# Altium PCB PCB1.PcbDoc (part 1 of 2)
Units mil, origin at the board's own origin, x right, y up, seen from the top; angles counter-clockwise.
Board outline 3937.01 x 3937.01 mil, 4 copper layers (Top Layer, Layer 1, Layer 2, Bottom Layer), stack 68.734 mil thick; 96 components, 71 nets, 353 pads, 281 vias.
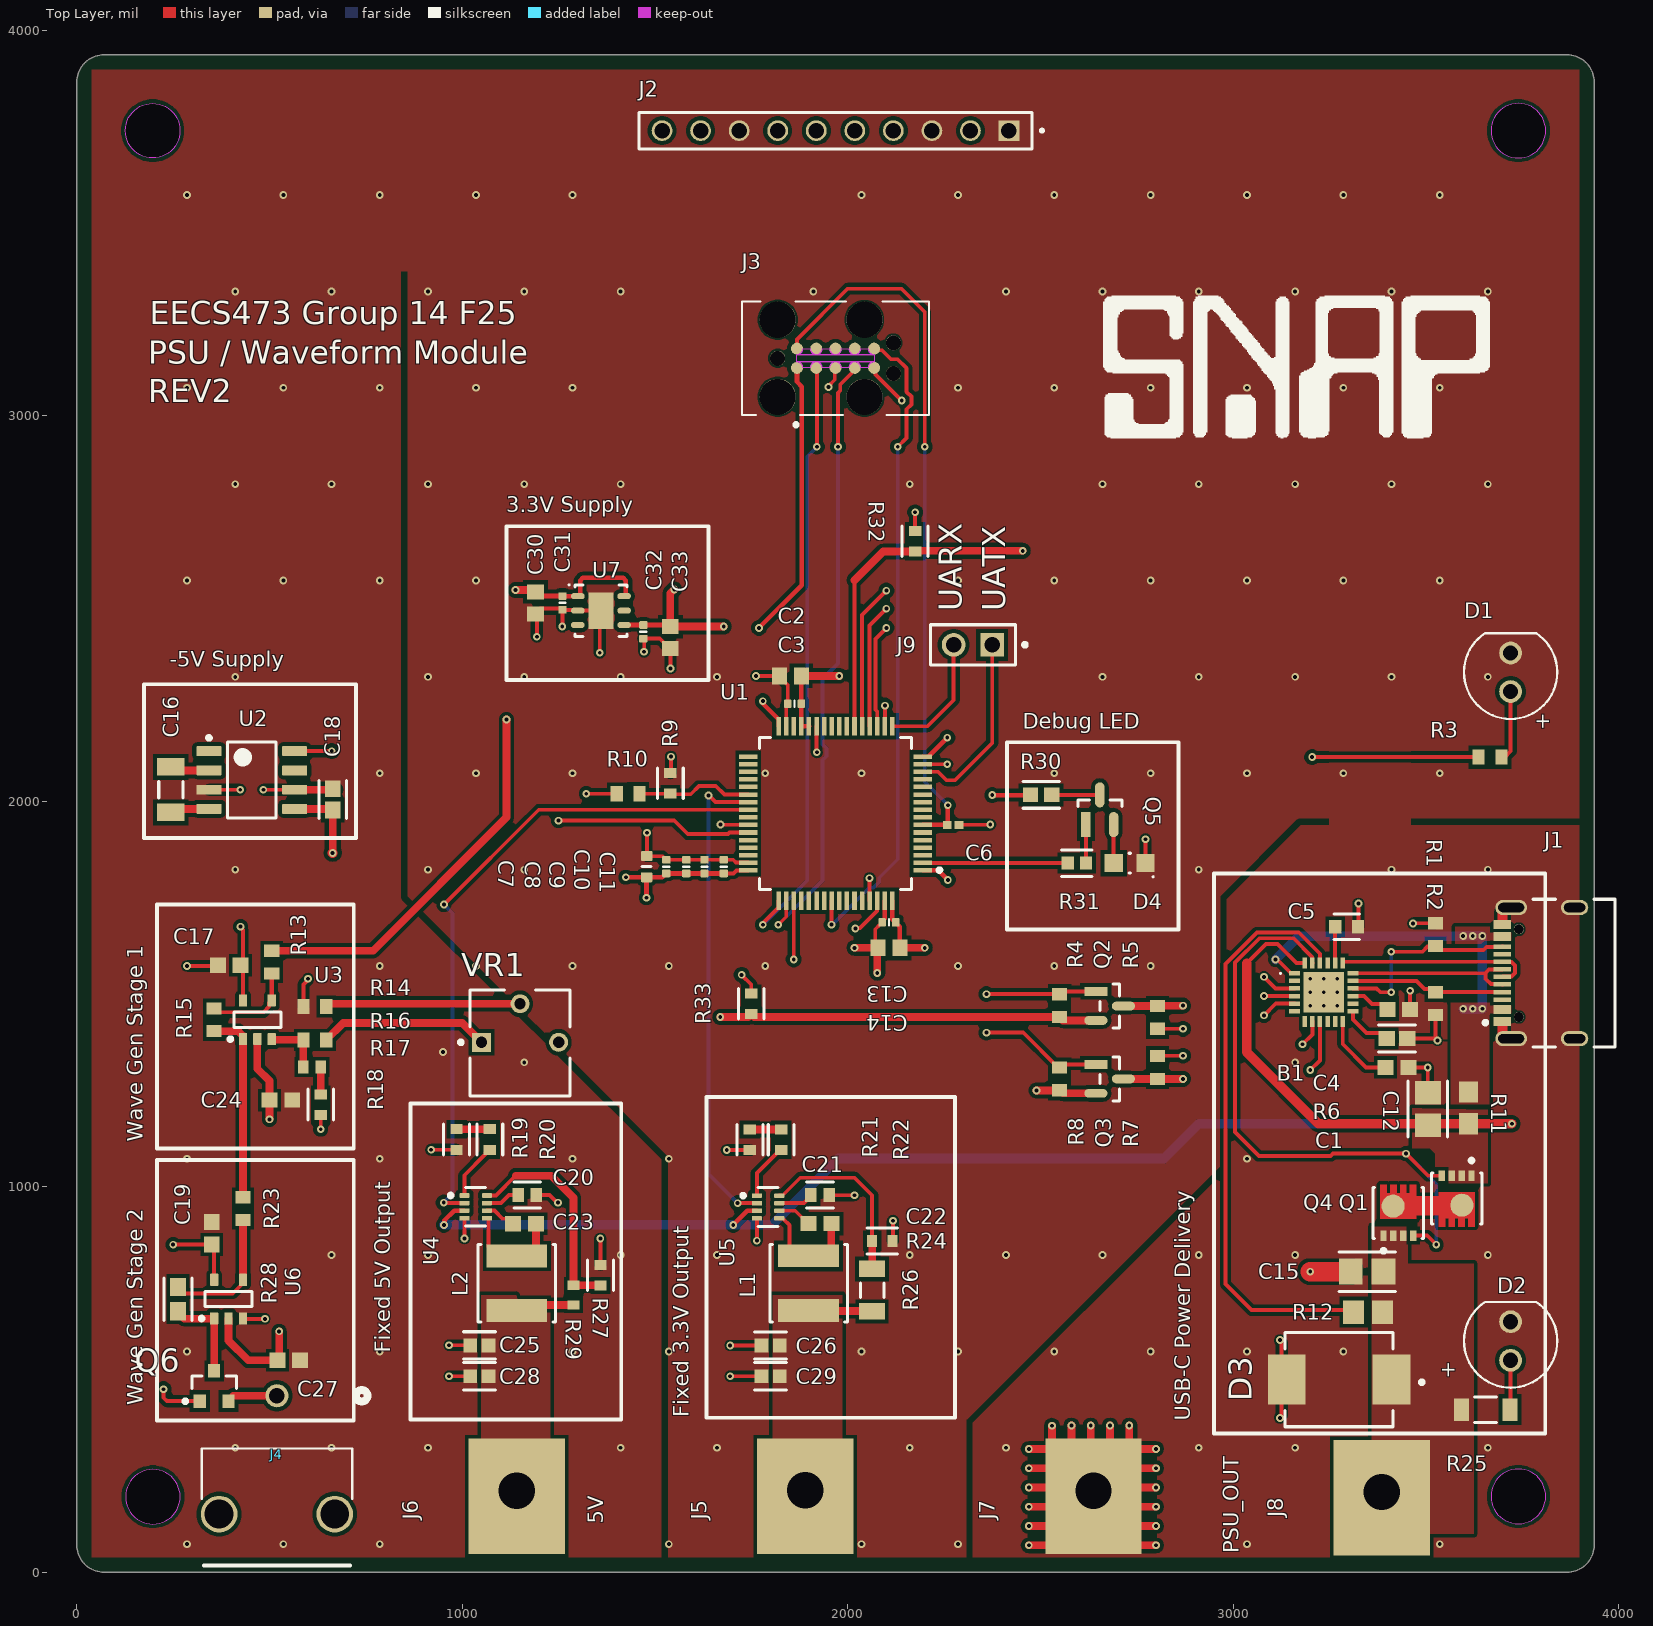
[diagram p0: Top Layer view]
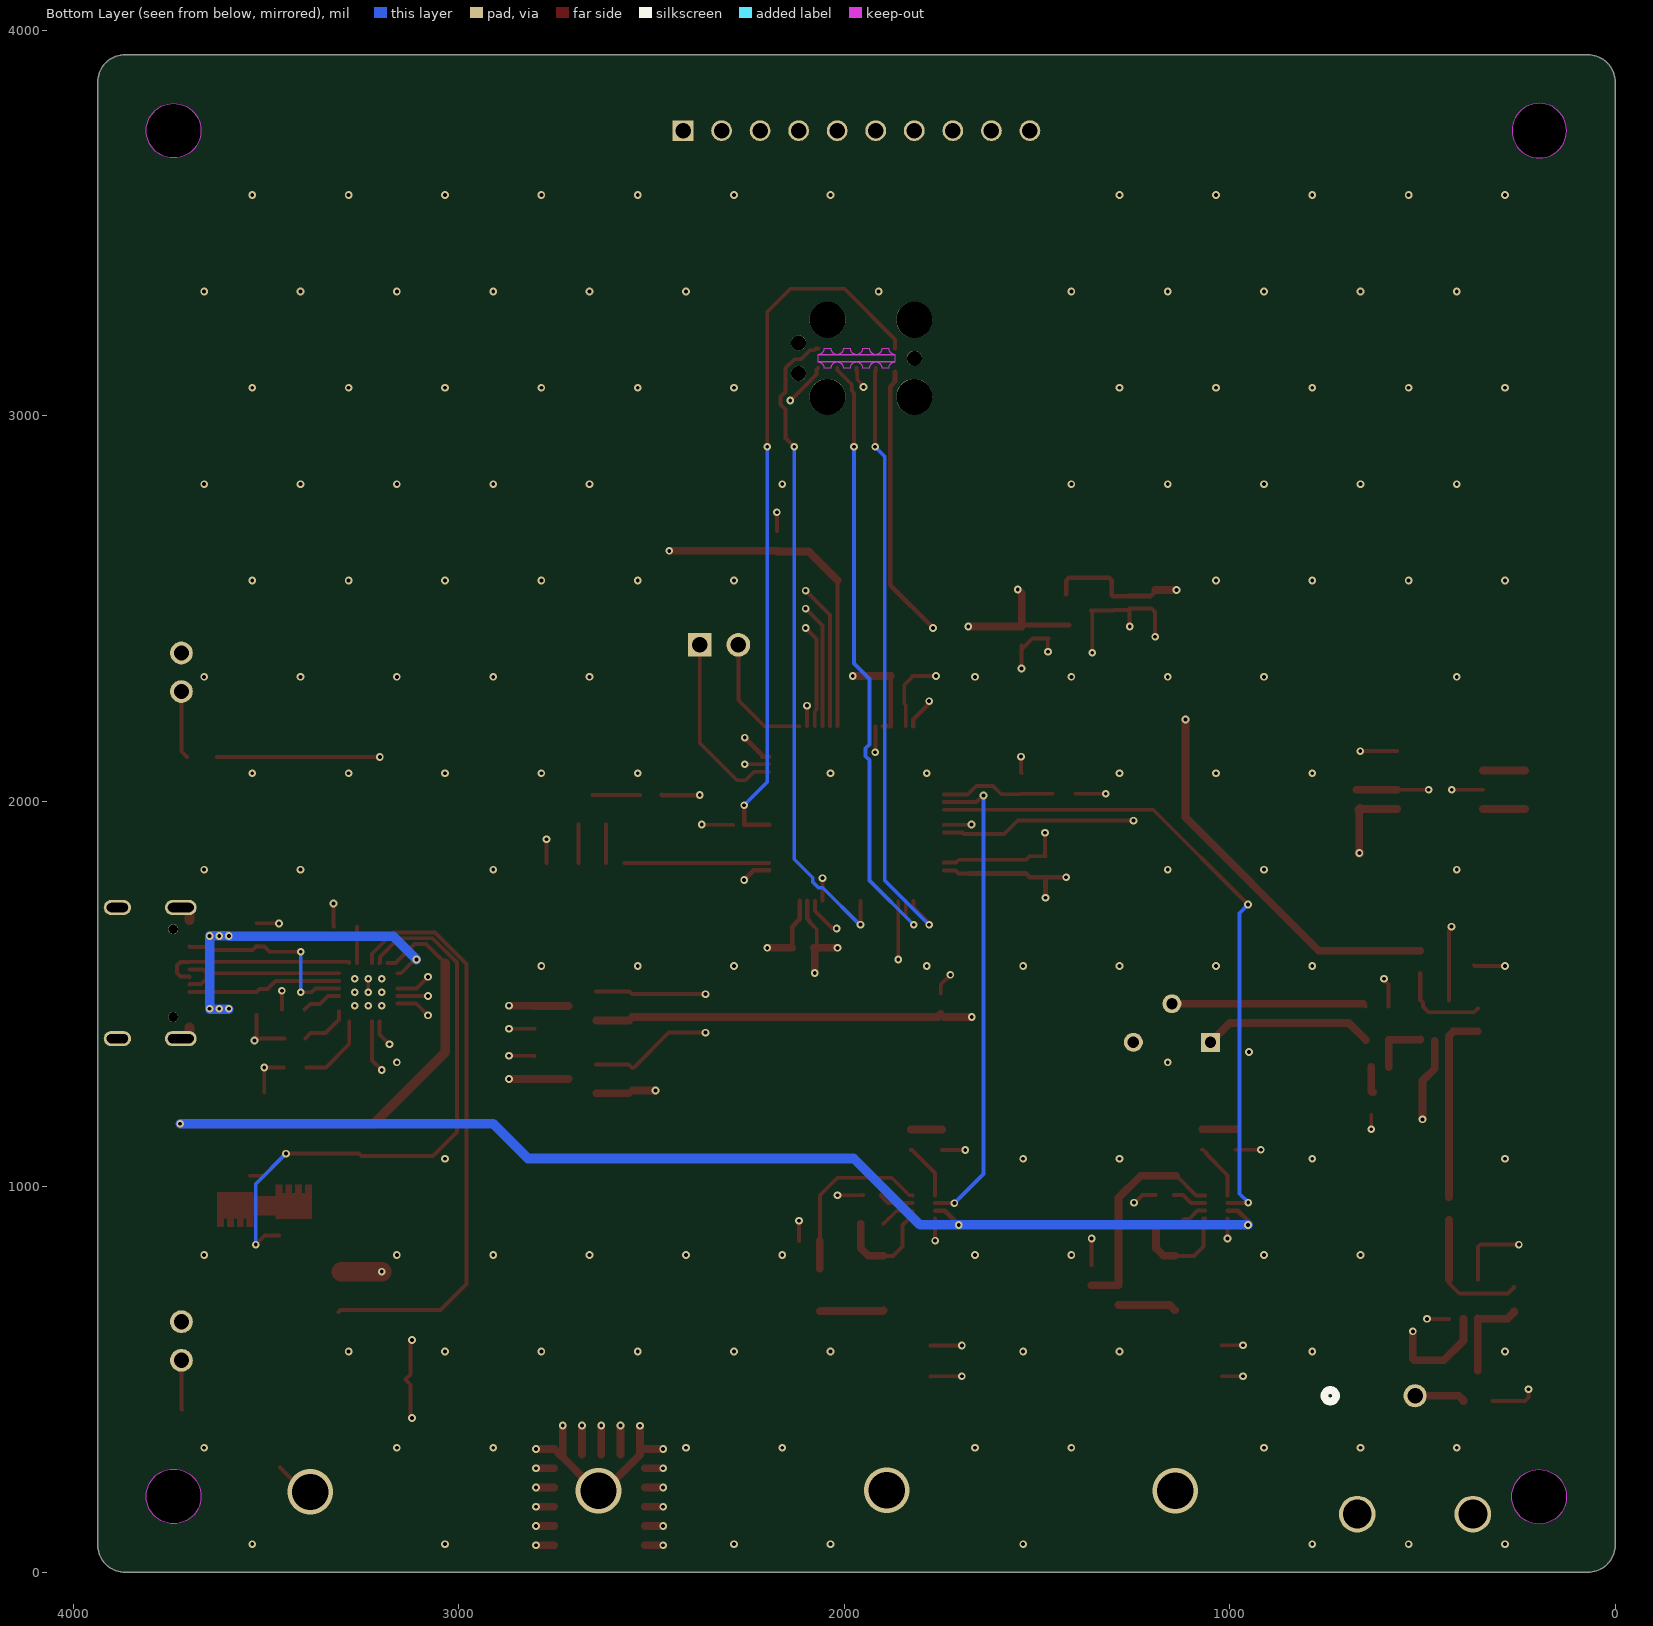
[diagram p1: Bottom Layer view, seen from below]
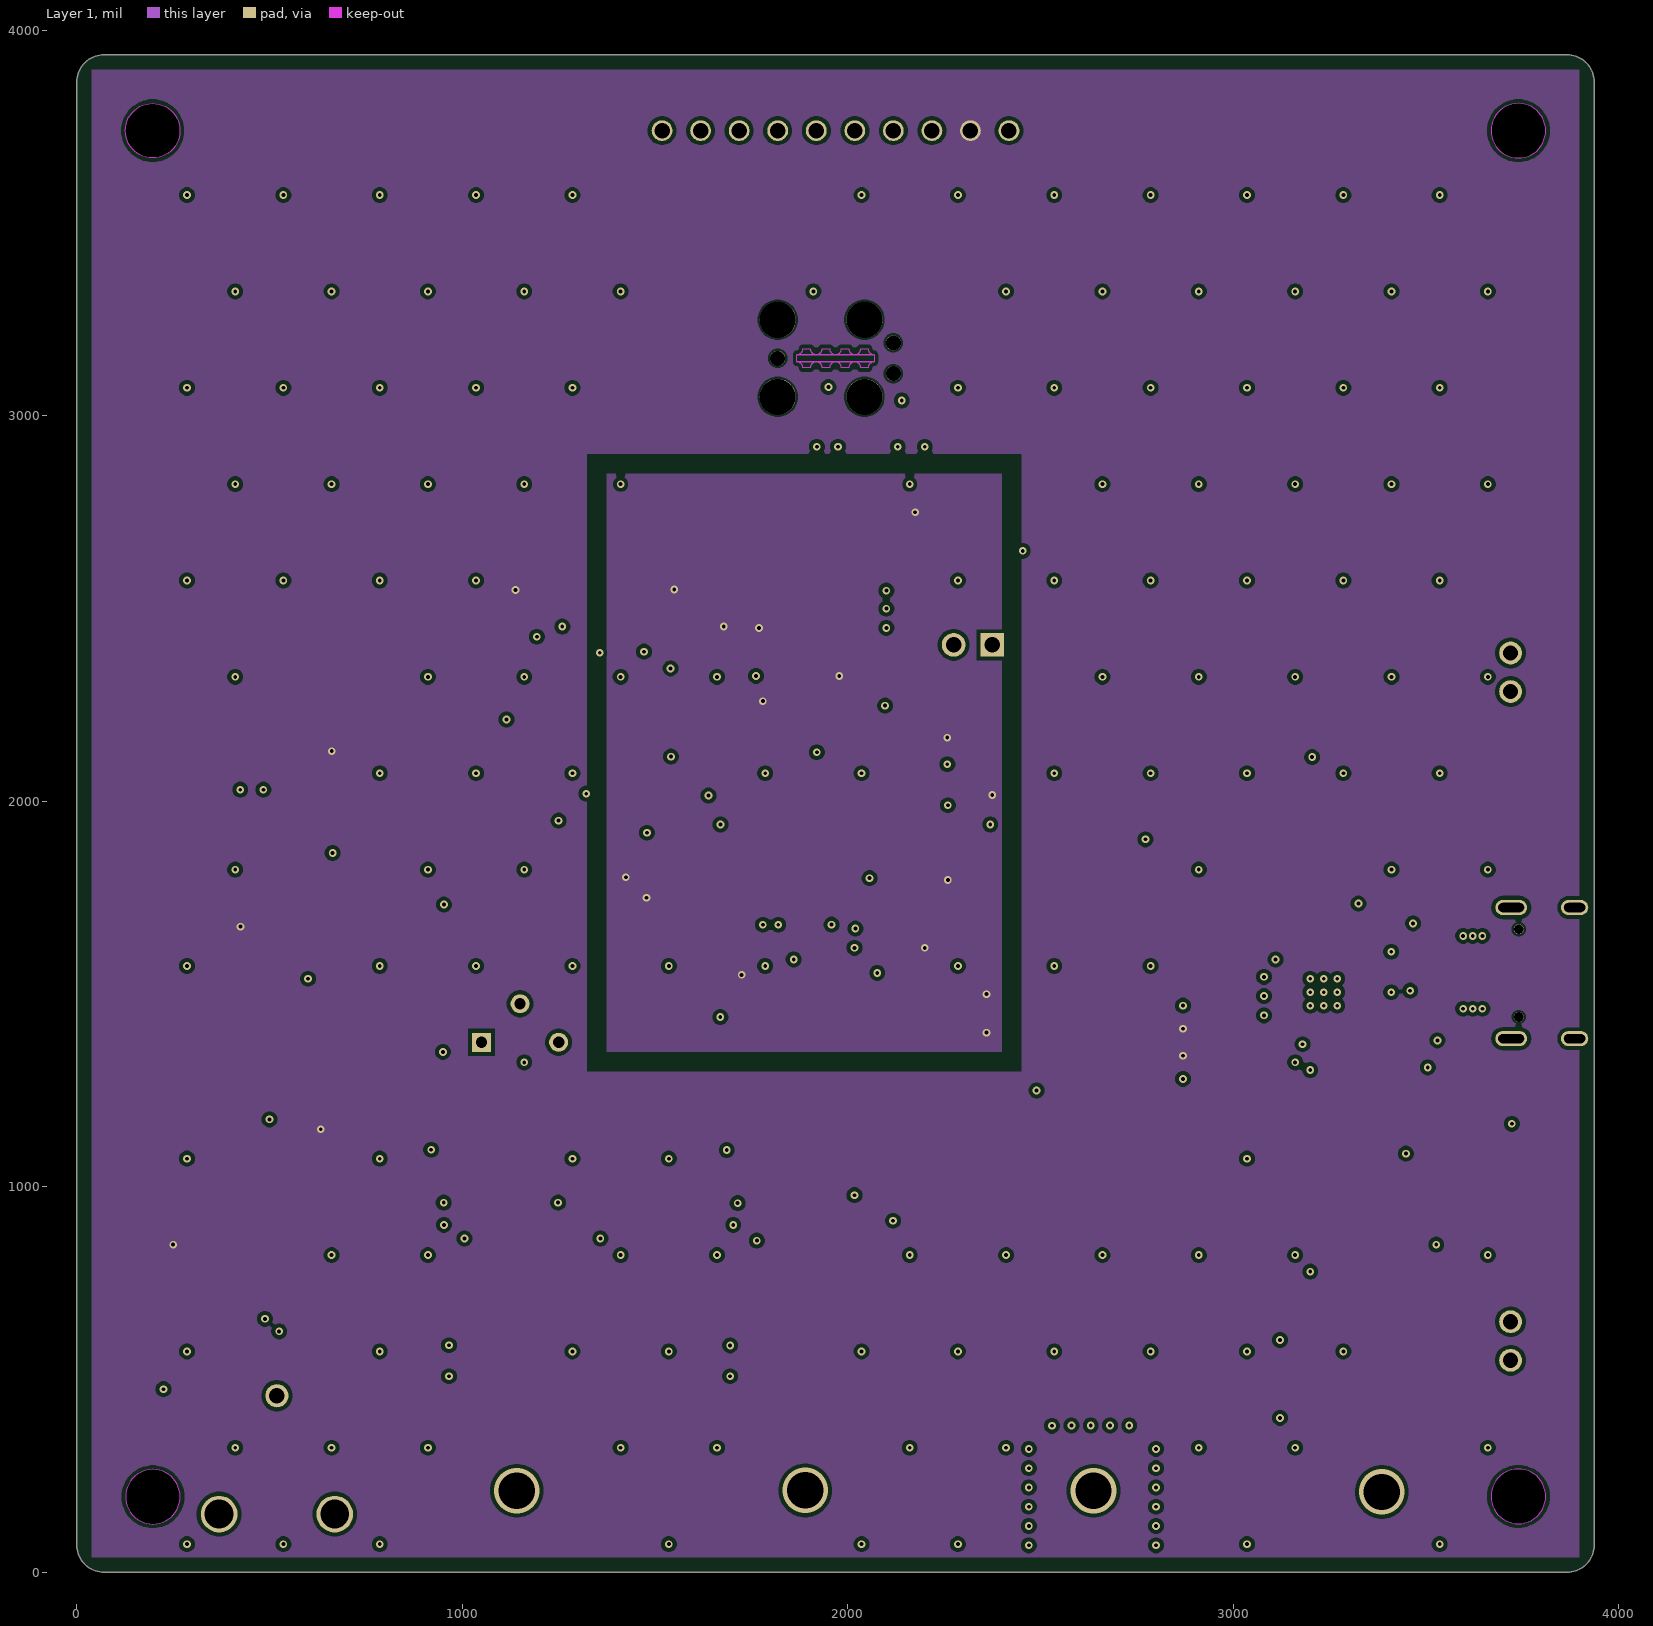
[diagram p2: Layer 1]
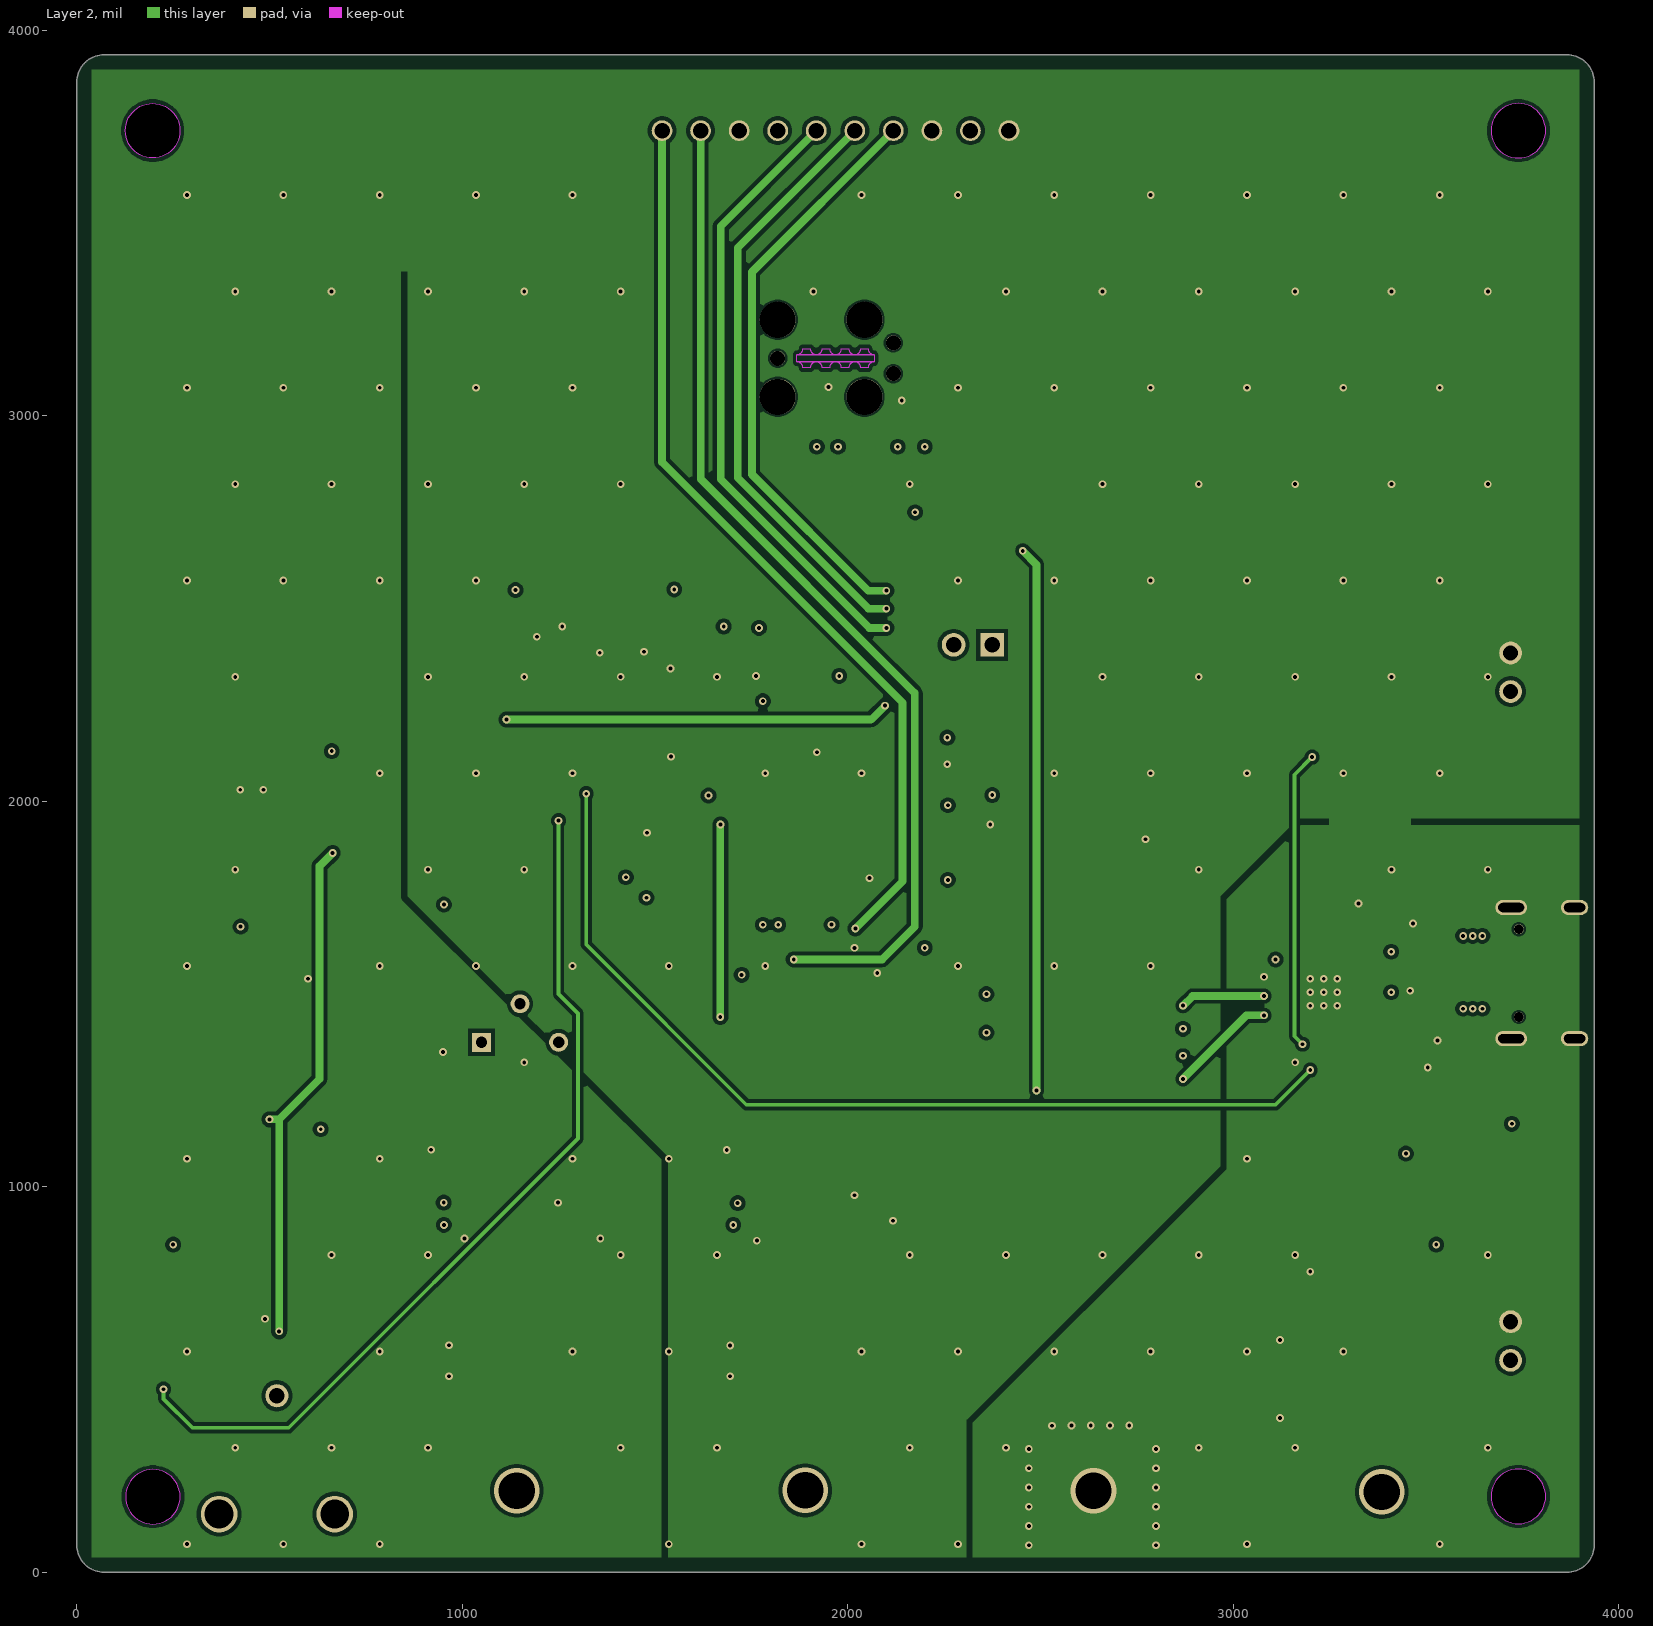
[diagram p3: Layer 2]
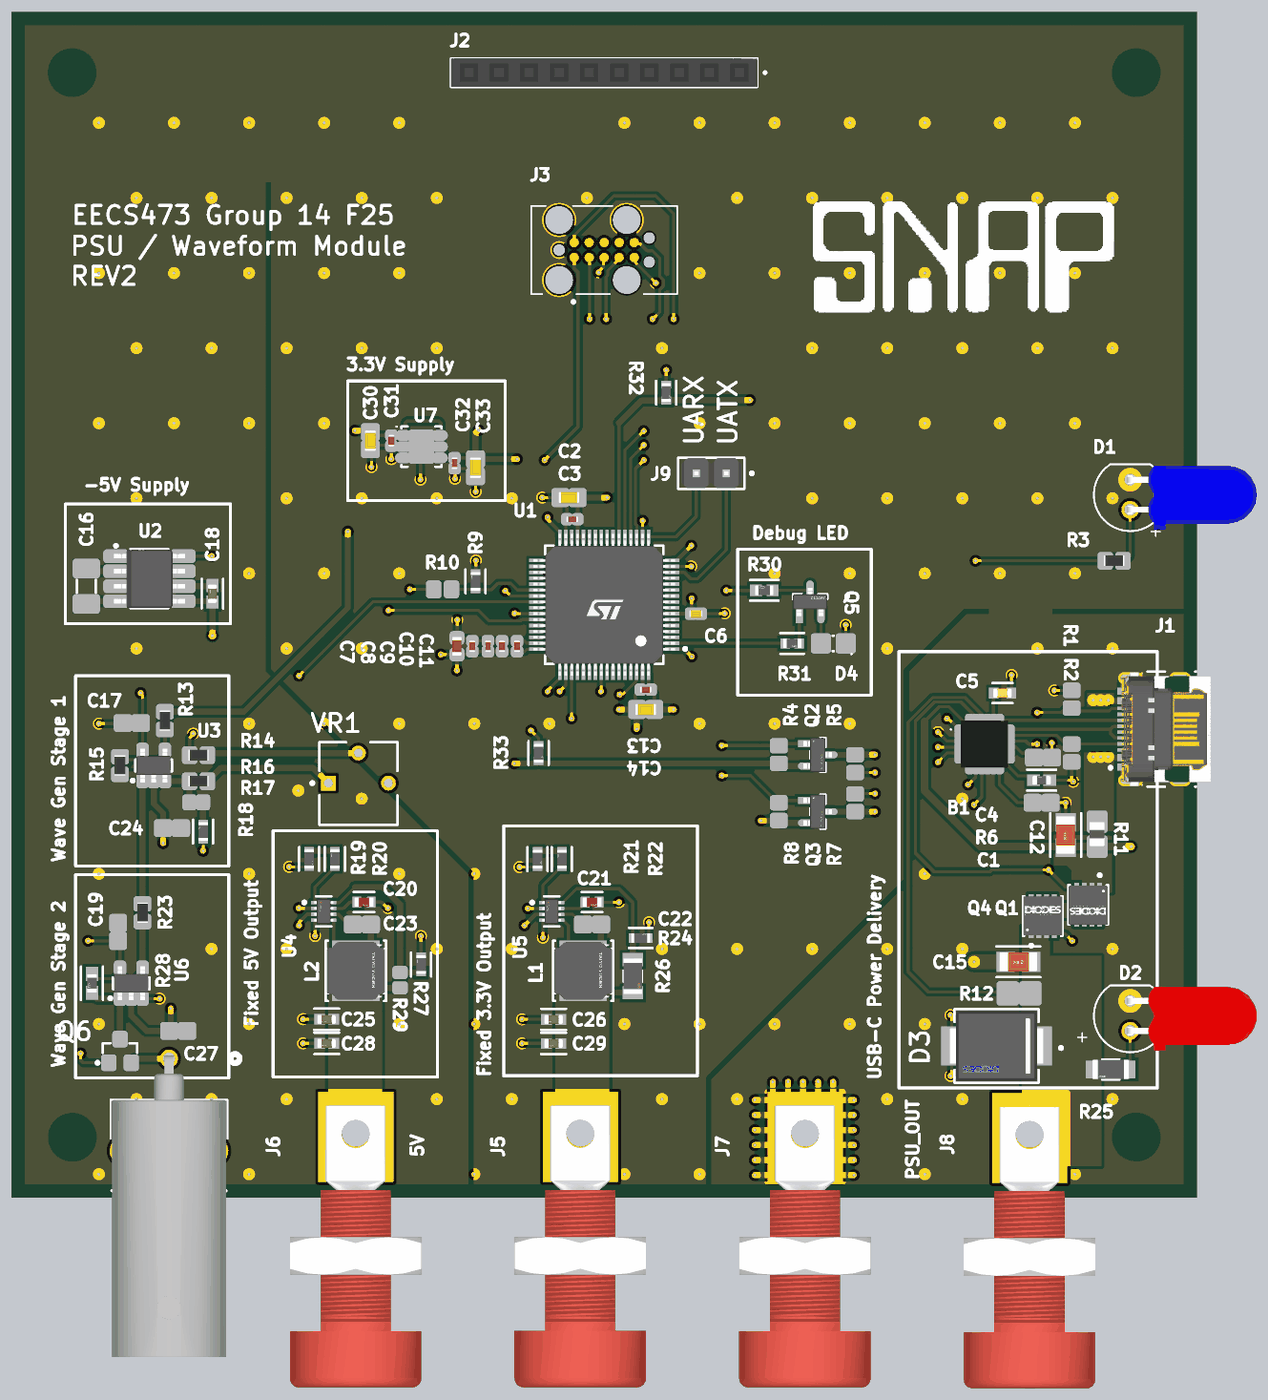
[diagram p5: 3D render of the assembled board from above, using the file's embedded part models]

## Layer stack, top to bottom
Top Solder: solder mask 0.5, Solder Resist, Dk 3.3
Top Layer: signal copper 1.378
Dielectric 1: prepreg 2.8, PP-006, Dk 4.1
Layer 1: signal copper 0.689
Dielectric1: core 59, FR-4, Dk 4.3
Layer 2: signal copper 0.689
Dielectric 2: prepreg 2.8, PP-006, Dk 4.1
Bottom Layer: signal copper 1.378
Bottom Solder: solder mask 0.5, Solder Resist, Dk 3.3

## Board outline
0,70.87 ccw(c70.87,70.87) 70.87,0 3866.14,0 ccw(c3866.14,70.87) 3937.01,70.87 3937.01,3866.14 ccw(c3866.14,3866.14) 3866.14,3937.01 70.87,3937.01 ccw(c70.87,3866.14) 0,3866.14
cut-out: 3669.29,3740.16 ccw(c3740.16,3740.16) 3740.16,3669.29 ccw(c3740.16,3740.16) 3811.02,3740.16 ccw(c3740.16,3740.16) 3740.16,3811.02 ccw(c3740.16,3740.16)
cut-out: 3669.29,196.85 ccw(c3740.16,196.85) 3740.16,125.98 ccw(c3740.16,196.85) 3811.02,196.85 ccw(c3740.16,196.85) 3740.16,267.72 ccw(c3740.16,196.85)
cut-out: 126.69,196.07 ccw(c197.56,196.07) 197.56,125.2 ccw(c197.56,196.07) 268.42,196.07 ccw(c197.56,196.07) 197.56,266.94 ccw(c197.56,196.07)
cut-out: 196.85,3669.29 cw(c196.85,3740.16) 125.98,3740.16 cw(c196.85,3740.16) 196.85,3811.02 cw(c196.85,3740.16) 267.72,3740.16 cw(c196.85,3740.16)

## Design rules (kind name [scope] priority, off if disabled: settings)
Clearance "Stitching GND" [IsStitchingVia and InNet('GND') vs (IsVia and (Not IsStitchingVia)) Or IsPad] p1: gap=5 ignorepadtopadclearanceinfootprint=FALSE
Clearance [All] p2: gap=10 ignorepadtopadclearanceinfootprint=FALSE except(3: Arc-Hole Track-Hole; 5: Arc-Arc Arc-Track Arc-SMDPad Track-Track Track-SMDPad SMDPad-SMDPad SMDPad-Hole THPad-Hole Via-Hole Fill-Hole Poly-Hole Region-Hole Text-Hole)
DiffPairsRouting [All] p1: maxlimit=10 minlimit=10 mostfreqgap=10 toplayer_minwidth=10 toplayer_maxwidth=10 toplayer_prefwidth=10 midlayer1_minwidth=10 midlayer1_maxwidth=10 midlayer1_prefwidth=10 midlayer2_minwidth=10 midlayer2_maxwidth=10 midlayer2_prefwidth=10 bottomlayer_minwidth=10 bottomlayer_maxwidth=10 bottomlayer_prefwidth=10 maxuncoupledlength=500
HoleSize [All] p1: absolutevalues=TRUE maxlimit=300 minlimit=6 maxpercent=80.000 minpercent=20.000
MinimumAnnularRing [All] p1: minimumring=5
PasteMaskExpansion [All] p1: expansion=10
PlaneClearance [All] p1: clearance=15
PlaneConnect [All] p1: pad.planeconnectstyle=Relief pad.reliefexpansion=20 pad.reliefentries=4 pad.reliefconductorwidth=10 pad.reliefairgap=10 via.planeconnectstyle=Direct via.reliefexpansion=20 via.reliefentries=4 via.reliefconductorwidth=10 via.reliefairgap=10
PolygonConnect PolygonConnect_1 [InNet('VBUS_SNS')] p1: connectstyle=Direct reliefconductorwidth=10 reliefentries=4 polygonreliefangle="90 Angle" airgapwidth=10
PolygonConnect PolygonConnect_5 [InNet('VBUS')] p2: connectstyle=Direct reliefconductorwidth=10 reliefentries=4 polygonreliefangle="90 Angle" airgapwidth=10
PolygonConnect PolygonConnect_4 [InNet('PSU_OUT')] p3: connectstyle=Direct reliefconductorwidth=10 reliefentries=4 polygonreliefangle="90 Angle" airgapwidth=10
PolygonConnect PolygonConnect_3 [InNet('NetC10_2')] p4: connectstyle=Direct reliefconductorwidth=10 reliefentries=4 polygonreliefangle="90 Angle" airgapwidth=10
PolygonConnect PolygonConnect_2 [InNet('NetC6_2')] p5: connectstyle=Direct reliefconductorwidth=10 reliefentries=4 polygonreliefangle="90 Angle" airgapwidth=10
PolygonConnect [All] p6: connectstyle=Direct reliefconductorwidth=10 reliefentries=4 polygonreliefangle="90 Angle" airgapwidth=10
RoutingVias [All] p1: holewidth=10 width=20 viastyle="Through Hole" minholewidth=10 minwidth=20 maxholewidth=10 maxwidth=20
SMDNeckDown [All] p1: percent=120.000
SilkToSolderMaskClearance SilkscreenOverComponentPads [IsPad] p1: minsilkscreentomaskgap=4 clearancetoexposedcopper=TRUE
SolderMaskExpansion [All] p1: expansion=10 istentingtop=FALSE
SupplyNets "Schematic Supply Nets_2" [InNet('-5')] p1: voltage=0.000
SupplyNets "Schematic Supply Nets_5" [InNet('GND')] p2: voltage=0.000
SupplyNets "Schematic Supply Nets_4" [InNet('3V3')] p3: voltage=0.000
SupplyNets "Schematic Supply Nets" [InNet('+5')] p4: voltage=0.000
Width [All] p1: maxlimit=50 minlimit=10 preferedwidth=20 minimp=50.000000 maximp=50.000000 favimp=50.000000
24 further rules are at their usual default settings.

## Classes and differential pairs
component class WG1: C16 C17 C18 C19 C24 C27 Q6 R13 R14 R15 R16 R17 R18 R23 R28 U2 U3 U6 VR1
component class TopLevel: J2 J4 J5 J6 J7 J8 J9 R32 R33
component class MCU1: C2 C3 C6 C7 C8 C9 C10 C11 C13 C14 C30 C31 C32 C33 D4 J3 Q5 R30 R31 U1 U7
component class PS1: B1 C1 C4 C5 C12 C15 C20 C21 C22 C23 C25 C26 C28 C29 D1 D2 D3 J1 L1 L2 Q1 Q2 Q3 Q4 R1 R2 R3 R4 R5 R6 R7 R8 R9 R10 R11 R12 R19 R20 R21 R22 R24 R25 R26 R27 R29 U4 U5

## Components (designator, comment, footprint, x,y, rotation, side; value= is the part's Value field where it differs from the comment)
B1 "AP33772S" AP33772SDKZ13FA01 3235.16,1504.84 r0 top
C1 ".1uF" CAPC1608X90X35NL15T15 3425.16,1309.84 r0 top
C2 "Capacitor 1uF +/- 10% 16V 0603" CAPC1608X90X35ML15T15 1851.38,2325.49 r0 top value=1µF
C3 "Capacitor 100nF +/-20% 10V 0402" CAPC0402(1005)60_L 1862.2,2253.38 r0 top value=100nF
C4 ".1uF" CAPC1608X90X35NL15T15 3429.68,1459.84 r180 top
C5 "1uF" FP-CC0603-DA-MFG 3294.69,1674.84 r0 top value="1 uF"
C6 "Capacitor 0.1 uF +/- 5% 16 V 0402" CAPC1005X56X25LL10T15 2273.86,1938.98 r180 top value=100nF
C7 "Capacitor 4.7µF +/-20% 10V 0603" CAPC0603(1608)100_L 1478.5,1830.71 r270 top value=4.7µF
C8 "Capacitor 100nF +/-20% 10V 0402" CAPC0402(1005)60_L 1529.49,1830.71 r270 top value=100nF
C9 "Capacitor 100nF +/-20% 10V 0402" CAPC0402(1005)60_L 1581.34,1830.71 r270 top value=100nF
C10 "Capacitor 100nF +/-20% 10V 0402" CAPC0402(1005)60_L 1628.5,1830.71 r270 top value=100nF
C11 "Capacitor 100nF +/-20% 10V 0402" CAPC0402(1005)60_L 1678.5,1830.71 r270 top value=100nF
C12 "10uF" FP-C3216-160-0_2-IPC_C 3505.16,1202.21 r90 top
C13 "Capacitor 100nF +/-20% 10V 0402" CAPC0402(1005)60_L 2107.01,1686.06 r0 top value=100nF
C14 "Capacitor 1uF +/- 10% 16V 0603" CAPC1608X90X35ML15T15 2107.01,1620 r0 top value=1µF
C15 "10uF" FP-C3216-160-0_2-IPC_C 3347.83,780.03 r180 top
C16 "CAP 47uF 10V 1206(3216)" CAPC1206(3216)190_N 244.14,2030.35 r90 top value=47uF
C17 ".1uF" CAPC1608X90X35NL15T15 395.47,1575 r0 top
C18 "10uF" FP-GRM188-0_2-IPC_B 664.14,2005.35 r90 top
C19 ".1uF" CAPC1608X90X35NL15T15 350,879.53 r270 top
C20 "33nF" FP-C0603C333J4REC7411-MFG 1168.73,979 r0 top
C21 "33nF" FP-C0603C333J4REC7411-MFG 1928.12,978.76 r0 top
C22 ".1uF" CAPC1608X90X35NL15T15 1928.12,904.46 r0 top
C23 ".1uF" CAPC1608X90X35NL15T15 1161.73,904 r0 top
C24 ".1uF" CAPC1608X90X35NL15T15 529.53,1225 r180 top
C25 "22uF" FP-GRM188-0_2-IPC_C 1044.41,588.59 r180 top
C26 "22uF" FP-GRM188-0_2-IPC_C 1800.07,588.36 r180 top
C27 ".1uF" CAPC1608X90X35NL15T15 550,550 r180 top
C28 "22uF" FP-GRM188-0_2-IPC_C 1044.41,508.59 r180 top
C29 "22uF" FP-GRM188-0_2-IPC_C 1800.07,508.36 r180 top
C30 "Capacitor 1uF +/- 10% 16V 0603" CAPC1608X90X35ML15T15 1190,2515 r90 top value=1µF
C31 "Capacitor 100nF +/-20% 10V 0402" CAPC0402(1005)60_L 1260,2515 r90 top value=100nF
C32 "Capacitor 100nF +/-20% 10V 0402" CAPC0402(1005)60_L 1470,2440 r90 top value=100nF
C33 "Capacitor 1uF +/- 10% 16V 0603" CAPC1608X90X35ML15T15 1540,2425 r90 top value=1µF
D1 "5mm Blue LED" WL-TMRC_D5.9H8.7 3720,2334.99 r90 top
D2 "5mm Red LED" WL-TMRC_D5.9H8.7 3720.01,599.99 r90 top
D3 "B550C-13-F" FP-SMC-MFG 3275,500 r180 top
D4 "LTST-C170KGKT" LTST-LTST-C170KGKT-2_V 2731.46,1839.89 r180 top
J1 "USB4105-GF-A" FP-USB4105-GF-A-MFG 3840.16,1554.53 r90 top
J2 "SSQ-110-04-G-S" SAMTEC_SSQ-110-04-G-S 1968.5,3740.16 r180 top
J3 "TC2050-IDC" TAG-CONNECT_TC2050-IDC 1968.5,3149.61 r0 top
J4 "731713150" CONN_731713150_MOL 519.29,457.9 r0 top
J5 "108-0902-001" FP-108-0902-001-MFG 1889.76,262.27 r0 top
J6 "108-0902-001" FP-108-0902-001-MFG 1141.73,261.85 r0 top
J7 "108-0902-001" FP-108-0902-001-MFG 2637.8,261.85 r0 top
J8 "108-0902-001" FP-108-0902-001-MFG 3385.83,258.36 r0 top
J9 "M20-9990246" FP-M20-9990246-MFG 2325,2406.3 r180 top
L1 "3.3uH" FP-NR5040-H_4_1-MFG 1898.58,750.09 r270 top
L2 "3.3uH" FP-NR5040-H_4_1-MFG 1141.73,750 r270 top
Q1 "DMT6010LFG-7" FP-PowerDI3333-8-MFG 3580.16,969.84 r180 top
Q2 "BSS138" FP-318-08-IPC_B 2679.68,1469.06 r0 top
Q3 "BSS138" FP-318-08-IPC_B 2679.68,1280 r0 top
Q4 "DMT6010LFG-7" FP-PowerDI3333-8-MFG 3428.59,932.37 r0 top
Q5 "MMBT3904-7-F" FP-SOT23-IPC_A 2654.09,1978.35 r90 top
Q6 "BC818-40LT1G" ONSC-SOT-23-3-318-08_V 356.3,483.27 r90 top
R1 "5.1k" RESC1608X55X25ML10T15 3525.16,1654.37 r270 top
R2 "5.1k" RESC1608X55X25ML10T15 3525.16,1475.32 r90 top
R3 "Resistor 1k +/-1% 0603 100 mW" RESC1608X55X25ML10T15 3666.58,2115 r0 top value=1k
R4 "5.1k" RESC1608X55X25ML10T15 2550,1470 r90 top
R5 "5.1k" RESC1608X55X25ML10T15 2803.85,1439.53 r270 top
R6 "10k NTC" FP-NC_18-0_15-IPC_B 3425.16,1384.84 r180 top
R7 "5.1k" RESC1608X55X25ML10T15 2803.85,1309.53 r90 top
R8 "5.1k" RESC1608X55X25ML10T15 2550,1280 r90 top
R9 "10k" FP-RC0603-0_55-IPC_C 1540,2046.64 r90 top
R10 "5.1k" RESC1608X55X25ML10T15 1430.47,2020 r180 top
R11 "ERJ6LWFR005V" RES_ERJ6LWFR005V 3610.16,1204.84 r270 top value=5m
R12 "100" RESC2013X60X40ML20T25 3350,675 r0 top
R13 "Resistor 1k +/-1% 0603 100 mW" RESC1608X55X25ML10T15 505.91,1583.07 r90 top value=1k
R14 "Resistor 1k +/-1% 0603 100 mW" RESC1608X55X25ML10T15 617.68,1467.99 r180 top value=1k
R15 "Resistor 1k +/-1% 0603 100 mW" RESC1608X55X25ML10T15 356.3,1433.54 r90 top value=1k
R16 "Resistor 1k +/-1% 0603 100 mW" RESC1608X55X25ML10T15 617.68,1381.09 r0 top value=1k
R17 "100" RESC1609X50X30LL10T20 610.15,1311.06 r180 top
R18 "10k" FP-RC0603-0_55-IPC_C 632.79,1213.54 r90 top
R19 "10k" FP-RC0603-0_55-IPC_C 985.35,1122.77 r270 top
R20 "10k" FP-RC0603-0_55-IPC_C 1071.7,1122.77 r90 top
R21 "10k" FP-RC0603-0_55-IPC_C 1746.34,1122.04 r270 top
R22 "10k" FP-RC0603-0_55-IPC_C 1827.4,1122.04 r90 top
R23 "Resistor 1k +/-1% 0603 100 mW" RESC1608X55X25ML10T15 431.1,943.38 r90 top value=1k
R24 "10k" FP-RC0603-0_55-IPC_C 2090.18,859.51 r0 top
R25 "5k" FP-RT1206-0_65-MFG 3655.24,421.73 r180 top value=5kΩ
R26 "31.2k" FP-TFCR1206-IPC_B 2063.54,732.18 r270 top
R27 "10k" FP-RC0603-0_55-IPC_C 1358.73,771 r90 top
R28 "3k" FP-RMCF0603-IPC_A 262.76,708.66 r270 top
R29 "52.3k" RESC1608X55X25LL10T15 1288.73,719 r270 top
R30 "510R" FP-RMCF0603-IPC_B 2501.71,2016.8 r180 top
R31 "2k" FP-RMCF0603-IPC_C 2594.41,1839.89 r0 top
R32 "10k" FP-RC0603-0_55-IPC_C 2175,2675 r270 top
R33 "10k" FP-RC0603-0_55-IPC_C 1750,1475 r270 top
U1 "STM32G474RET6" FP-LQFP64-5W-MFG 1968.5,1968.5 r180 top
U2 "LM2663MX/NOPB" D0008A_M 454.14,2055.35 r0 top
U3 "OPA192IDBVR" DBV0005A_L 468.5,1433.54 r90 top
U4 "XTPS62933DRLR" FP-DRL0008A-MFG 1034.73,948 r0 top
U5 "XTPS62933DRLR" FP-DRL0008A-MFG 1793.54,947.76 r0 top
U6 "OPA192IDBVR" DBV0005A_L 393.7,708.66 r90 top
U7 "LD39050PU33R" DFN6D_M 1360,2495 r0 top
VR1 "3362P-1-103LF" BOUR-3362P 1150,1373.62 r0 top

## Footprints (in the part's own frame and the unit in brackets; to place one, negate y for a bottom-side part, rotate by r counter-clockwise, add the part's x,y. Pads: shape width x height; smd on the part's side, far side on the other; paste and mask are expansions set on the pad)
AP33772SDKZ13FA01 [mm]
  rect 0.75x0.3 smd: 1(-1.925,1.25) 2(-1.925,0.75) 3(-1.925,0.25) 4(-1.925,-0.25) 5(-1.925,-0.75) 6(-1.925,-1.25) 13(1.925,-1.25) 14(1.925,-0.75) 15(1.925,-0.25) 16(1.925,0.25) 17(1.925,0.75) 18(1.925,1.25)
  rect 0.3x0.75 smd: 7(-1.25,-1.925) 8(-0.75,-1.925) 9(-0.25,-1.925) 10(0.25,-1.925) 11(0.75,-1.925) 12(1.25,-1.925) 19(1.25,1.925) 20(0.75,1.925) 21(0.25,1.925) 22(-0.25,1.925) 23(-0.75,1.925) 24(-1.25,1.925)
  rect 2.7x2.7 smd: 25(0,0)
  silkscreen extent -2.9,1.2 -2.8,1.3, body extent -2,-2 2,2, height 0.75
BOUR-3362P [mm] "THD, 3-Leads, Body 6.6x6.99mm, Pitch 2.54mm"
  rect 1.25x1.25 hole 0.75: 1(-2.54,0.035)
  round 1.25 hole 0.75: 2(0,2.575) 3(2.54,0.035)
  silkscreen extent -4.02,-3.49 3.3,3.5, body extent -3.3,-3.49 3.3,3.49, height 4.95
CAPC0402(1005)60_L [mm] "Chip Capacitor, Body 1.0x0.5mm, Height 0.6mm, IPC High Density"
  rrect25% 0.5x0.55 smd: 1(-0.45,0) 2(0.45,0)
  silkscreen extent 0,-0.2 0,0.2, body extent -0.5,-0.25 0.5,0.25, height 0.6
CAPC0603(1608)100_L [mm] "Chip Capacitor, Body 1.6x0.8mm, Height 1.0mm, IPC High Density"
  rrect25% 0.66x0.76 smd: 1(-0.7,0) 2(0.7,0)
  silkscreen extent 0,-0.3 0,0.3, body extent -0.8,-0.4 0.8,0.4, height 0.95
CAPC1005X56X25LL10T15 [mm] "Chip Capacitor, 2-Leads, Body 1.10x0.60mm, IPC High Density"
  rect 0.58x0.54 smd: 1(-0.39,0) 2(0.39,0)
  body extent -0.55,-0.3 0.55,0.3, height 0.56
CAPC1206(3216)190_N [mm] "Chip Capacitor, Body 3.2x1.6mm, Height 1.9mm, IPC Medium Density"
  rect 1.15x1.8 smd: 1(-1.5,0) 2(1.5,0)
  silkscreen extent -0.55,-0.8 0.55,0.8, body extent -1.7,-0.9 1.7,0.9, height 1.9
CAPC1608X90X35ML15T15 [mm] "Chip Capacitor, 2-Leads, Body 1.75x0.95mm, IPC Low Density"
  rect 1x1.1 smd: 1(-0.725,0) 2(0.725,0)
  body extent -0.87,-0.48 0.87,0.48, height 0.9
CAPC1608X90X35NL15T15 [mm] "Chip Capacitor, 2-Leads, Body 1.60x0.81mm, IPC Medium Density"
  rect 1.05x1 smd: 1(-0.75,0) 2(0.75,0)
  body extent -0.88,-0.48 0.87,0.48, height 0.9
CONN_731713150_MOL [mil]
  round 60 hole 40: 1(0,0)
  round 95 hole 75: 2(-150,-307) 3(150,-307)
  silkscreen extent -195,-440 235,15, body extent -190,-996 190,10, height 368
D0008A_M [mm] "SOIC, 8-Leads, Body 5x4mm, Pitch 1.27mm, IPC Low Density"
  rrect15% 1.65x0.65 smd: 1(-2.825,1.905) 2(-2.825,0.635) 3(-2.825,-0.635) 4(-2.825,-1.905) 5(2.825,-1.905) 6(2.825,-0.635) 7(2.825,0.635) 8(2.825,1.905)
  silkscreen extent -2.95,-2.5 1.6,2.9, body extent -3,-2.45 3,2.45, height 1.63
DBV0005A_L [mm] "SOT23, 5-Leads, Body 3.05x1.75mm, Pitch 0.95mm, IPC High Density"
  rrect18% 0.8x0.55 smd: 1(-1.275,0.95) 2(-1.275,0) 3(-1.275,-0.95) 4(1.275,-0.95) 5(1.275,0.95)
  silkscreen extent -1.4,-1.55 0.5,1.9, body extent -1.42,-1.46 1.42,1.46, height 1.08
DFN6D_M [mm] "SON, 6-Leads, Body 3x3mm, Pitch 0.95mm, Thermal Pad 2.4x1.65mm, IPC Low Density"
  oval 0.9x0.4 smd: 1(-1.525,0.95) 2(-1.525,0) 3(-1.525,-0.95) 4(1.525,-0.95) 5(1.525,0) 6(1.525,0.95)
  rect 1.65x2.4 smd: 7(0,0)
  silkscreen extent -2.15,-1.7 1.7,1.75, body extent -1.55,-1.55 1.55,1.55, height 0.95
FP-108-0902-001-MFG [mil]
  rect 250x300 / inner rect 0x0 / far side rect 0x0 all layers, no hole: 1(0,-65)
  body extent -220,-899 218,39, height 264
FP-318-08-IPC_B [mm]
  rect 1.524x0.578 smd paste+0 mask+0: 1(-0.91,0.95)
  rrect100% 1.524x0.578 smd paste+0 mask+0: 2(-0.91,-0.95) 3(0.91,0)
  silkscreen extent -0.65,-1.45 0.65,1.45, body extent -1.92,-1.7 1.92,1.7, height 0.25
FP-C0603C333J4REC7411-MFG [mm]
  rect 0.75x0.9 smd paste+0 mask+0: 1(-0.6,0) 2(0.6,0)
  silkscreen extent -0.87,-0.85 0.88,0.85, body extent -1.2,-0.6 1.2,0.6, height 0.25
FP-C3216-160-0_2-IPC_C [mil]
  rect 61.18x67.17 smd paste+0 mask+0: 1(-42.37,0) 2(42.37,0)
  silkscreen extent -73,-51 73,51, body extent -77,-39 77,39, height 10
FP-CC0603-DA-MFG [mm]
  rect 0.8x0.9 smd paste+0 mask+0: 1(-0.75,0) 2(0.75,0)
  silkscreen extent -0.85,-0.85 0.85,0.85, body extent -1.35,-0.75 1.35,0.75, height 0.25
FP-DRL0008A-MFG [mm]
  rrect33% 0.67x0.3 smd paste+0 mask+0: 1(-0.74,0.75) 2(-0.74,0.25) 3(-0.74,-0.25) 4(-0.74,-0.75) 5(0.74,-0.75) 6(0.74,-0.25) 7(0.74,0.25) 8(0.74,0.75)
  silkscreen extent -1.77,-1.27 0.65,1.28, body extent -1.17,-1.35 1.17,1.35, height 0.25
FP-GRM188-0_2-IPC_B [mil]
  rect 43.51x39.61 smd paste+0 mask+0: 1(-27.58,0) 2(27.58,0)
  silkscreen extent -49,-36 49,36, body extent -59,-30 59,30, height 10
FP-GRM188-0_2-IPC_C [mil]
  rect 35.63x35.68 smd paste+0 mask+0: 1(-23.64,0) 2(23.64,0)
  silkscreen extent -41,-35 41,35, body extent -45,-24 45,24, height 10
FP-LQFP64-5W-MFG [mm]
  rect 1.2x0.3 smd paste+0 mask+0: 1(-5.75,3.75) 2(-5.75,3.25) 3(-5.75,2.75) 4(-5.75,2.25) 5(-5.75,1.75) 6(-5.75,1.25) 7(-5.75,0.75) 8(-5.75,0.25) 9(-5.75,-0.25) 10(-5.75,-0.75) 11(-5.75,-1.25) 12(-5.75,-1.75) 13(-5.75,-2.25) 14(-5.75,-2.75) 15(-5.75,-3.25) 16(-5.75,-3.75) 33(5.75,-3.75) 34(5.75,-3.25) 35(5.75,-2.75) 36(5.75,-2.25) 37(5.75,-1.75) 38(5.75,-1.25) 39(5.75,-0.75) 40(5.75,-0.25) 41(5.75,0.25) 42(5.75,0.75) 43(5.75,1.25) 44(5.75,1.75) 45(5.75,2.25) 46(5.75,2.75) 47(5.75,3.25) 48(5.75,3.75)
  rect 0.3x1.2 smd paste+0 mask+0: 17(-3.75,-5.75) 18(-3.25,-5.75) 19(-2.75,-5.75) 20(-2.25,-5.75) 21(-1.75,-5.75) 22(-1.25,-5.75) 23(-0.75,-5.75) 24(-0.25,-5.75) 25(0.25,-5.75) 26(0.75,-5.75) 27(1.25,-5.75) 28(1.75,-5.75) 29(2.25,-5.75) 30(2.75,-5.75) 31(3.25,-5.75) 32(3.75,-5.75) 49(3.75,5.75) 50(3.25,5.75) 51(2.75,5.75) 52(2.25,5.75) 53(1.75,5.75) 54(1.25,5.75) 55(0.75,5.75) 56(0.25,5.75) 57(-0.25,5.75) 58(-0.75,5.75) 59(-1.25,5.75) 60(-1.75,5.75) 61(-2.25,5.75) 62(-2.75,5.75) 63(-3.25,5.75) 64(-3.75,5.75)
  silkscreen extent -6.98,-5 5,5, body extent -6.45,-6.45 6.45,6.45, height 0.25
FP-M20-9990246-MFG [mm]
  rect 1.57x1.57 hole 1.02 paste-2539.97 mask+0: 1(-1.27,0)
  round 1.57 hole 1.02 paste-2539.97 mask+0: 2(1.27,0)
  silkscreen extent -3.55,-1.32 2.79,1.32, body extent -2.89,-1.42 2.89,1.42, height 0.25
FP-NC_18-0_15-IPC_B [mil]
  rect 43.55x37.73 smd paste+0 mask+0: 1(-26.62,0) 2(26.62,0)
  silkscreen extent -48,-35 48,35, body extent -58,-29 58,29, height 10
FP-NR5040-H_4_1-MFG [mm]
  rect 1.5x4 smd paste+0 mask+0: 1(-1.8,0) 2(1.8,0)
  silkscreen extent -2.55,-2.55 2.55,2.55, body extent -2.65,-2.65 2.65,2.65, height 0.25
FP-PowerDI3333-8-MFG [mm]
  rect 0.42x0.7 smd paste+0 mask+0: 1(-0.975,-1.5) 2(-0.325,-1.5) 3(0.325,-1.5) 4(0.975,-1.5)
  round 1.519 smd paste+0 mask+0: 5-6-7-8(-0.341,0.444)
  Top Layer region: -1.185,1.85 -0.765,1.85 -0.765,1.31 -0.535,1.31 -0.535,1.85 -0.115,1.85 -0.115,1.31 0.115,1.31 0.115,1.85 0.535,1.85 0.535,1.31 0.765,1.31 0.765,1.85 1.185,1.85 1.185,-0.4 -1.185,-0.4 -1.185,1.85
  silkscreen extent -1.68,-2.62 1.67,1.67, body extent -1.78,-1.95 1.78,1.95, height 0.25
FP-RC0603-0_55-IPC_C [mil]
  rect 25.93x31.97 smd paste+0 mask+0: 1(-26.64,0) 2(26.64,0)
  silkscreen extent -40,-33 40,33, body extent -44,-22 44,22, height 10
FP-RMCF0603-IPC_A [mil]
  rect 47.48x41.66 smd paste+0 mask+0: 1(-31.54,0) 2(31.54,0)
  silkscreen extent -55,-37 55,37, body extent -75,-41 75,41, height 10
FP-RMCF0603-IPC_B [mil]
  rect 39.61x37.73 smd paste+0 mask+0: 1(-27.6,0) 2(27.6,0)
  silkscreen extent -47,-35 47,35, body extent -57,-29 57,29, height 10
FP-RMCF0603-IPC_C [mil]
  rect 31.73x33.79 smd paste+0 mask+0: 1(-23.66,0) 2(23.66,0)
  silkscreen extent -40,-34 40,34, body extent -43,-23 43,23, height 10
FP-RT1206-0_65-MFG [mm]
  rect 1x1.5 smd paste+0 mask+0: 1(-1.6,0) 2(1.6,0)
  silkscreen extent -0.73,-0.85 0.72,0.85, body extent -2.2,-0.95 2.2,0.95, height 0.25
FP-SMC-MFG [mm]
  rect 2.5x3.3 smd paste+0 mask+0: 1(-3.45,0) 2(3.45,0)
  silkscreen extent -5.58,-3.11 3.55,3.11, body extent -4.8,-3.21 4.8,3.21, height 0.25
FP-SOT23-IPC_A [mm]
  rect 1.659x0.627 smd paste+0 mask+0: 1(-0.977,0.915)
  rrect100% 1.659x0.627 smd paste+0 mask+0: 2(-0.977,-0.915) 3(0.977,0)
  silkscreen extent 0.23,-1.45 0.65,1.45, body extent -2.31,-1.95 2.31,1.95, height 0.25
FP-TFCR1206-IPC_B [mil]
  rect 43.53x67.25 smd paste+0 mask+0: 1(-55.17,0) 2(55.17,0)
  silkscreen extent -19,-31 19,31, body extent -87,-43 87,43, height 10
FP-USB4105-GF-A-MFG [mm]
  rrect100% 1x2.1 hole 1.7 slot 0.6 at 0 deg paste-2539.97 mask+0: 1(-4.32,3.015) 2(4.32,3.015)
  rrect100% 1x1.8 hole 1.4 slot 0.6 at 0 deg paste-2539.97 mask+0: 3(-4.32,-1.165) 4(4.32,-1.165)
  rect 0.6x1.15 smd paste+0 mask+0: A1-B12(-3.2,3.59) A4-B9(-2.4,3.59) B1-A12(3.2,3.59) B4-A9(2.4,3.59)
  rect 0.3x1.15 smd paste+0 mask+0: A5(-1.25,3.59) A6(-0.25,3.59) A7(0.25,3.59) A8(1.25,3.59) B5(1.75,3.59) B6(0.75,3.59) B7(-0.75,3.59) B8(-1.75,3.59)
  round 0.65 hole 0.65 unplated paste-2539.97 mask+0: ""(-2.89,2.515) ""(2.89,2.515)
  silkscreen extent -4.87,-3.84 4.86,4.84, body extent -4.96,-3.94 4.96,4.27, height 0.25
LTST-LTST-C170KGKT-2_V [mm] "SMD, 2-Leads, Body 2.00x1.25mm"
  rect 1.2x1.2 smd: 1(-1.05,0) 2(1.05,0)
  silkscreen extent -1.6,-0.65 0.05,0.95, body extent -1,-0.63 1,0.63, height 1.1
ONSC-SOT-23-3-318-08_V [mm] "SOT23, 3-Leads, Body 2.92x1.3mm, Pitch 0.95mm"
  rect 0.9x0.8 smd: 1(-1,0.95) 2(-1,-0.95) 3(1,0)
  silkscreen extent -1.12,-1.46 0.65,2.02, body extent -0.65,-1.46 0.65,1.46, height 1.11
RES_ERJ6LWFR005V [mm]
  rect 1.4x1.25 smd: 1(-1.05,0) 2(1.05,0)
  body extent -1,-0.63 1,0.63, height 0.7
RESC1608X55X25LL10T15 [mm] "Chip Resistor, 2-Leads, Body 1.60x0.80mm, IPC High Density"
  rect 0.6x0.8 smd: 1(-0.65,0) 2(0.65,0)
  body extent -0.85,-0.45 0.85,0.45, height 0.55
RESC1608X55X25ML10T15 [mm] "Chip Resistor, 2-Leads, Body 1.60x0.80mm, IPC Low Density"
  rect 0.8x1 smd: 1(-0.75,0) 2(0.75,0)
  body extent -0.85,-0.45 0.85,0.45, height 0.55
RESC1609X50X30LL10T20 [mm] "Chip Resistor, 2-Leads, Body 1.55x0.85mm, IPC High Density"
  rect 0.7x0.85 smd: 1(-0.575,0) 2(0.575,0)
  body extent -0.82,-0.48 0.82,0.48, height 0.5
RESC2013X60X40ML20T25 [mm] "Chip Resistor, 2-Leads, Body 2.00x1.25mm, IPC Low Density"
  rect 1.4x1.55 smd: 1(-0.95,0) 2(0.95,0)
  body extent -1.1,-0.72 1.1,0.72, height 0.6
SAMTEC_SSQ-110-04-G-S [mm]
  rect 1.37x1.37 / inner round 1.37 / far side rect 1.37x1.37 hole 1.02: 01(-11.43,0)
  round 1.37 hole 1.02: 02(-8.89,0) 03(-6.35,0) 04(-3.81,0) 05(-1.27,0) 06(1.27,0) 07(3.81,0) 08(6.35,0) 09(8.89,0) 10(11.43,0)
  silkscreen extent -13.7,-1.2 12.96,1.2, body extent -12.95,-1.21 12.95,1.21, height 8.51
TAG-CONNECT_TC2050-IDC [mil]
  round 31 smd paste-39.37: 1(-100,-25) 2(-50,-25) 3(0,-25) 4(50,-25) 5(100,-25) 6(100,25) 7(50,25) 8(0,25) 9(-50,25) 10(-100,25)
  round 93.5 hole 93.5 unplated: ""(-150,-100) ""(-150,100) ""(75,100)
  round 39 hole 39 unplated: ""(-150,0)
  round 93.5 hole 93.5 unplated mask+5: ""(75,-100)
  round 39 hole 39 unplated mask+3: ""(150,-39.96)
  round 39 hole 39 unplated mask+5: ""(150,39.96)
  Keep-Out Layer region: -50.83,-9.53 -51.61,-9.57 -52.44,-9.68 -53.23,-9.84 -54.02,-10.04 -54.8,-10.28 -55.55,-10.51 -56.3,-10.83 -57.05,-11.18 -57.76,-11.57 -58.43,-12.01 -59.09,-12.44 -59.76,-12.95 -60.35,-13.46 -60.94,-14.06 -61.54,-14.65 -62.05,-15.24 -62.56,-15.91 -62.99,-16.57 -63.43,-17.24 -63.82,-17.95 -64.17,-18.7 -64.49,-19.45 -64.72,-20.2 -64.96,-20.98 -65.16,-21.77 -65.32,-22.56 -65.43,-23.39 -65.47,-24.17 -65.51,-25 -84.49,-25 -84.53,-24.17 -84.57,-23.39 -84.68,-22.56 -84.84,-21.77 -85.04,-20.98 -85.28,-20.2 -85.51,-19.45 -85.83,-18.7 -86.18,-17.95 -86.57,-17.24 -87.01,-16.57 -87.44,-15.91 -87.95,-15.24 -88.46,-14.65 -89.06,-14.06 -89.65,-13.46 -90.24,-12.95 -90.91,-12.44 -91.57,-12.01 -92.24,-11.57 -92.95,-11.18 -93.7,-10.83 -94.45,-10.51 -95.2,-10.28 -95.98,-10.04 -96.77,-9.84 -97.56,-9.68 -98.39,-9.57 -99.17,-9.53 -99.75,-9.5 -100,-9.5 -100,-9.49 -99.75,-9.5 -50,-9.49
  Keep-Out Layer region: -0.83,-9.53 -1.61,-9.57 -2.44,-9.68 -3.23,-9.84 -4.02,-10.04 -4.8,-10.28 -5.55,-10.51 -6.3,-10.83 -7.05,-11.18 -7.76,-11.57 -8.43,-12.01 -9.09,-12.44 -9.76,-12.95 -10.35,-13.46 -10.94,-14.06 -11.54,-14.65 -12.05,-15.24 -12.56,-15.91 -12.99,-16.57 -13.43,-17.24 -13.82,-17.95 -14.17,-18.7 -14.49,-19.45 -14.72,-20.2 -14.96,-20.98 -15.16,-21.77 -15.32,-22.56 -15.43,-23.39 -15.47,-24.17 -15.51,-25 -34.49,-25 -34.53,-24.17 -34.57,-23.39 -34.68,-22.56 -34.84,-21.77 -35.04,-20.98 -35.28,-20.2 -35.51,-19.45 -35.83,-18.7 -36.18,-17.95 -36.57,-17.24 -37.01,-16.57 -37.44,-15.91 -37.95,-15.24 -38.46,-14.65 -39.06,-14.06 -39.65,-13.46 -40.24,-12.95 -40.91,-12.44 -41.57,-12.01 -42.24,-11.57 -42.95,-11.18 -43.7,-10.83 -44.45,-10.51 -45.2,-10.28 -45.98,-10.04 -46.77,-9.84 -47.56,-9.68 -48.39,-9.57 -49.17,-9.53 -49.75,-9.5 -50,-9.5 -50,-9.49 -49.75,-9.5 0,-9.49
  Keep-Out Layer region: 99.17,-9.53 98.39,-9.57 97.56,-9.68 96.77,-9.84 95.98,-10.04 95.2,-10.28 94.45,-10.51 93.7,-10.83 92.95,-11.18 92.24,-11.57 91.57,-12.01 90.91,-12.44 90.24,-12.95 89.65,-13.46 89.06,-14.06 88.46,-14.65 87.95,-15.24 87.44,-15.91 87.01,-16.57 86.57,-17.24 86.18,-17.95 85.83,-18.7 85.51,-19.45 85.28,-20.2 85.04,-20.98 84.84,-21.77 84.68,-22.56 84.57,-23.39 84.53,-24.17 84.49,-25 65.51,-25 65.47,-24.17 65.43,-23.39 65.32,-22.56 65.16,-21.77 64.96,-20.98 64.72,-20.2 64.49,-19.45 64.17,-18.7 63.82,-17.95 63.43,-17.24 62.99,-16.57 62.56,-15.91 62.05,-15.24 61.54,-14.65 60.94,-14.06 60.35,-13.46 59.76,-12.95 59.09,-12.44 58.43,-12.01 57.76,-11.57 57.05,-11.18 56.3,-10.83 55.55,-10.51 54.8,-10.28 54.02,-10.04 53.23,-9.84 52.44,-9.68 51.61,-9.57 50.83,-9.53 50.25,-9.5 50,-9.5 50,-9.49 50.25,-9.5 100,-9.49
  Keep-Out Layer region: 49.17,-9.53 48.39,-9.57 47.56,-9.68 46.77,-9.84 45.98,-10.04 45.2,-10.28 44.45,-10.51 43.7,-10.83 42.95,-11.18 42.24,-11.57 41.57,-12.01 40.91,-12.44 40.24,-12.95 39.65,-13.46 39.06,-14.06 38.46,-14.65 37.95,-15.24 37.44,-15.91 37.01,-16.57 36.57,-17.24 36.18,-17.95 35.83,-18.7 35.51,-19.45 35.28,-20.2 35.04,-20.98 34.84,-21.77 34.68,-22.56 34.57,-23.39 34.53,-24.17 34.49,-25 15.51,-25 15.47,-24.17 15.43,-23.39 15.32,-22.56 15.16,-21.77 14.96,-20.98 14.72,-20.2 14.49,-19.45 14.17,-18.7 13.82,-17.95 13.43,-17.24 12.99,-16.57 12.56,-15.91 12.05,-15.24 11.54,-14.65 10.94,-14.06 10.35,-13.46 9.76,-12.95 9.09,-12.44 8.43,-12.01 7.76,-11.57 7.05,-11.18 6.3,-10.83 5.55,-10.51 4.8,-10.28 4.02,-10.04 3.23,-9.84 2.44,-9.68 1.61,-9.57 0.83,-9.53 0.25,-9.5 0,-9.5 0,-9.49 0.25,-9.5 50,-9.49
  Keep-Out Layer region: -65.47,24.17 -65.43,23.39 -65.32,22.56 -65.16,21.77 -64.96,20.98 -64.72,20.2 -64.49,19.45 -64.17,18.7 -63.82,17.95 -63.43,17.24 -62.99,16.57 -62.56,15.91 -62.05,15.24 -61.54,14.65 -60.94,14.06 -60.35,13.46 -59.76,12.95 -59.09,12.44 -58.43,12.01 -57.76,11.57 -57.05,11.18 -56.3,10.83 -55.55,10.51 -54.8,10.28 -54.02,10.04 -53.23,9.84 -52.44,9.69 -51.61,9.57 -50.83,9.53 -50.25,9.5 -50,9.5 -50,9.49 -50.25,9.5 -100,9.49 -99.17,9.53 -98.39,9.57 -97.56,9.69 -96.77,9.84 -95.98,10.04 -95.2,10.28 -94.45,10.51 -93.7,10.83 -92.95,11.18 -92.24,11.57 -91.57,12.01 -90.91,12.44 -90.24,12.95 -89.65,13.46 -89.06,14.06 -88.46,14.65 -87.95,15.24 -87.44,15.91 -87.01,16.57 -86.57,17.24 -86.18,17.95 -85.83,18.7 -85.51,19.45 -85.28,20.2 -85.04,20.98 -84.84,21.77 -84.68,22.56 -84.57,23.39 -84.53,24.17 -84.49,25 -65.51,25
  Keep-Out Layer region: -15.47,24.17 -15.43,23.39 -15.32,22.56 -15.16,21.77 -14.96,20.98 -14.72,20.2 -14.49,19.45 -14.17,18.7 -13.82,17.95 -13.43,17.24 -12.99,16.57 -12.56,15.91 -12.05,15.24 -11.54,14.65 -10.94,14.06 -10.35,13.46 -9.76,12.95 -9.09,12.44 -8.43,12.01 -7.76,11.57 -7.05,11.18 -6.3,10.83 -5.55,10.51 -4.8,10.28 -4.02,10.04 -3.23,9.84 -2.44,9.69 -1.61,9.57 -0.83,9.53 -0.25,9.5 0,9.5 0,9.49 -0.25,9.5 -50,9.49 -49.17,9.53 -48.39,9.57 -47.56,9.69 -46.77,9.84 -45.98,10.04 -45.2,10.28 -44.45,10.51 -43.7,10.83 -42.95,11.18 -42.24,11.57 -41.57,12.01 -40.91,12.44 -40.24,12.95 -39.65,13.46 -39.06,14.06 -38.46,14.65 -37.95,15.24 -37.44,15.91 -37.01,16.57 -36.57,17.24 -36.18,17.95 -35.83,18.7 -35.51,19.45 -35.28,20.2 -35.04,20.98 -34.84,21.77 -34.68,22.56 -34.57,23.39 -34.53,24.17 -34.49,25 -15.51,25
  Keep-Out Layer region: 34.53,24.17 34.57,23.39 34.68,22.56 34.84,21.77 35.04,20.98 35.28,20.2 35.51,19.45 35.83,18.7 36.18,17.95 36.57,17.24 37.01,16.57 37.44,15.91 37.95,15.24 38.46,14.65 39.06,14.06 39.65,13.46 40.24,12.95 40.91,12.44 41.57,12.01 42.24,11.57 42.95,11.18 43.7,10.83 44.45,10.51 45.2,10.28 45.98,10.04 46.77,9.84 47.56,9.69 48.39,9.57 49.17,9.53 49.75,9.5 50,9.5 50,9.49 49.75,9.5 0,9.49 0.83,9.53 1.61,9.57 2.44,9.69 3.23,9.84 4.02,10.04 4.8,10.28 5.55,10.51 6.3,10.83 7.05,11.18 7.76,11.57 8.43,12.01 9.09,12.44 9.76,12.95 10.35,13.46 10.94,14.06 11.54,14.65 12.05,15.24 12.56,15.91 12.99,16.57 13.43,17.24 13.82,17.95 14.17,18.7 14.49,19.45 14.72,20.2 14.96,20.98 15.16,21.77 15.32,22.56 15.43,23.39 15.47,24.17 15.51,25 34.49,25
  Keep-Out Layer region: 84.53,24.17 84.57,23.39 84.68,22.56 84.84,21.77 85.04,20.98 85.28,20.2 85.51,19.45 85.83,18.7 86.18,17.95 86.57,17.24 87.01,16.57 87.44,15.91 87.95,15.24 88.46,14.65 89.06,14.06 89.65,13.46 90.24,12.95 90.91,12.44 91.57,12.01 92.24,11.57 92.95,11.18 93.7,10.83 94.45,10.51 95.2,10.28 95.98,10.04 96.77,9.84 97.56,9.69 98.39,9.57 99.17,9.53 99.75,9.5 100,9.5 100,9.49 99.75,9.5 50,9.49 50.83,9.53 51.61,9.57 52.44,9.69 53.23,9.84 54.02,10.04 54.8,10.28 55.55,10.51 56.3,10.83 57.05,11.18 57.76,11.57 58.43,12.01 59.09,12.44 59.76,12.95 60.35,13.46 60.94,14.06 61.54,14.65 62.05,15.24 62.56,15.91 62.99,16.57 63.43,17.24 63.82,17.95 64.17,18.7 64.49,19.45 64.72,20.2 64.96,20.98 65.16,21.77 65.32,22.56 65.43,23.39 65.47,24.17 65.51,25 84.49,25
  Keep-Out Layer region: 100,-9.5 -100,-9.5 -100,0 -100,9.5 100,9.5
  Keep-Out Layer region: -50.83,-9.53 -51.61,-9.57 -52.44,-9.68 -53.23,-9.84 -54.02,-10.04 -54.8,-10.28 -55.55,-10.51 -56.3,-10.83 -57.05,-11.18 -57.76,-11.57 -58.43,-12.01 -59.09,-12.44 -59.76,-12.95 -60.35,-13.46 -60.94,-14.06 -61.54,-14.65 -62.05,-15.24 -62.56,-15.91 -62.99,-16.57 -63.43,-17.24 -63.82,-17.95 -64.17,-18.7 -64.49,-19.45 -64.72,-20.2 -64.96,-20.98 -65.16,-21.77 -65.32,-22.56 -65.43,-23.39 -65.47,-24.17 -65.51,-25 -84.49,-25 -84.53,-24.17 -84.57,-23.39 -84.68,-22.56 -84.84,-21.77 -85.04,-20.98 -85.28,-20.2 -85.51,-19.45 -85.83,-18.7 -86.18,-17.95 -86.57,-17.24 -87.01,-16.57 -87.44,-15.91 -87.95,-15.24 -88.46,-14.65 -89.06,-14.06 -89.65,-13.46 -90.24,-12.95 -90.91,-12.44 -91.57,-12.01 -92.24,-11.57 -92.95,-11.18 -93.7,-10.83 -94.45,-10.51 -95.2,-10.28 -95.98,-10.04 -96.77,-9.84 -97.56,-9.68 -98.39,-9.57 -99.17,-9.53 -99.75,-9.5 -100,-9.5 -100,-9.49 -99.75,-9.5 -50,-9.49
  Keep-Out Layer region: -0.83,-9.53 -1.61,-9.57 -2.44,-9.68 -3.23,-9.84 -4.02,-10.04 -4.8,-10.28 -5.55,-10.51 -6.3,-10.83 -7.05,-11.18 -7.76,-11.57 -8.43,-12.01 -9.09,-12.44 -9.76,-12.95 -10.35,-13.46 -10.94,-14.06 -11.54,-14.65 -12.05,-15.24 -12.56,-15.91 -12.99,-16.57 -13.43,-17.24 -13.82,-17.95 -14.17,-18.7 -14.49,-19.45 -14.72,-20.2 -14.96,-20.98 -15.16,-21.77 -15.32,-22.56 -15.43,-23.39 -15.47,-24.17 -15.51,-25 -34.49,-25 -34.53,-24.17 -34.57,-23.39 -34.68,-22.56 -34.84,-21.77 -35.04,-20.98 -35.28,-20.2 -35.51,-19.45 -35.83,-18.7 -36.18,-17.95 -36.57,-17.24 -37.01,-16.57 -37.44,-15.91 -37.95,-15.24 -38.46,-14.65 -39.06,-14.06 -39.65,-13.46 -40.24,-12.95 -40.91,-12.44 -41.57,-12.01 -42.24,-11.57 -42.95,-11.18 -43.7,-10.83 -44.45,-10.51 -45.2,-10.28 -45.98,-10.04 -46.77,-9.84 -47.56,-9.68 -48.39,-9.57 -49.17,-9.53 -49.75,-9.5 -50,-9.5 -50,-9.49 -49.75,-9.5 0,-9.49
  Keep-Out Layer region: 99.17,-9.53 98.39,-9.57 97.56,-9.68 96.77,-9.84 95.98,-10.04 95.2,-10.28 94.45,-10.51 93.7,-10.83 92.95,-11.18 92.24,-11.57 91.57,-12.01 90.91,-12.44 90.24,-12.95 89.65,-13.46 89.06,-14.06 88.46,-14.65 87.95,-15.24 87.44,-15.91 87.01,-16.57 86.57,-17.24 86.18,-17.95 85.83,-18.7 85.51,-19.45 85.28,-20.2 85.04,-20.98 84.84,-21.77 84.68,-22.56 84.57,-23.39 84.53,-24.17 84.49,-25 65.51,-25 65.47,-24.17 65.43,-23.39 65.32,-22.56 65.16,-21.77 64.96,-20.98 64.72,-20.2 64.49,-19.45 64.17,-18.7 63.82,-17.95 63.43,-17.24 62.99,-16.57 62.56,-15.91 62.05,-15.24 61.54,-14.65 60.94,-14.06 60.35,-13.46 59.76,-12.95 59.09,-12.44 58.43,-12.01 57.76,-11.57 57.05,-11.18 56.3,-10.83 55.55,-10.51 54.8,-10.28 54.02,-10.04 53.23,-9.84 52.44,-9.68 51.61,-9.57 50.83,-9.53 50.25,-9.5 50,-9.5 50,-9.49 50.25,-9.5 100,-9.49
  Keep-Out Layer region: 49.17,-9.53 48.39,-9.57 47.56,-9.68 46.77,-9.84 45.98,-10.04 45.2,-10.28 44.45,-10.51 43.7,-10.83 42.95,-11.18 42.24,-11.57 41.57,-12.01 40.91,-12.44 40.24,-12.95 39.65,-13.46 39.06,-14.06 38.46,-14.65 37.95,-15.24 37.44,-15.91 37.01,-16.57 36.57,-17.24 36.18,-17.95 35.83,-18.7 35.51,-19.45 35.28,-20.2 35.04,-20.98 34.84,-21.77 34.68,-22.56 34.57,-23.39 34.53,-24.17 34.49,-25 15.51,-25 15.47,-24.17 15.43,-23.39 15.32,-22.56 15.16,-21.77 14.96,-20.98 14.72,-20.2 14.49,-19.45 14.17,-18.7 13.82,-17.95 13.43,-17.24 12.99,-16.57 12.56,-15.91 12.05,-15.24 11.54,-14.65 10.94,-14.06 10.35,-13.46 9.76,-12.95 9.09,-12.44 8.43,-12.01 7.76,-11.57 7.05,-11.18 6.3,-10.83 5.55,-10.51 4.8,-10.28 4.02,-10.04 3.23,-9.84 2.44,-9.68 1.61,-9.57 0.83,-9.53 0.25,-9.5 0,-9.5 0,-9.49 0.25,-9.5 50,-9.49
  Keep-Out Layer region: -65.47,24.17 -65.43,23.39 -65.32,22.56 -65.16,21.77 -64.96,20.98 -64.72,20.2 -64.49,19.45 -64.17,18.7 -63.82,17.95 -63.43,17.24 -62.99,16.57 -62.56,15.91 -62.05,15.24 -61.54,14.65 -60.94,14.06 -60.35,13.46 -59.76,12.95 -59.09,12.44 -58.43,12.01 -57.76,11.57 -57.05,11.18 -56.3,10.83 -55.55,10.51 -54.8,10.28 -54.02,10.04 -53.23,9.84 -52.44,9.69 -51.61,9.57 -50.83,9.53 -50.25,9.5 -50,9.5 -50,9.49 -50.25,9.5 -100,9.49 -99.17,9.53 -98.39,9.57 -97.56,9.69 -96.77,9.84 -95.98,10.04 -95.2,10.28 -94.45,10.51 -93.7,10.83 -92.95,11.18 -92.24,11.57 -91.57,12.01 -90.91,12.44 -90.24,12.95 -89.65,13.46 -89.06,14.06 -88.46,14.65 -87.95,15.24 -87.44,15.91 -87.01,16.57 -86.57,17.24 -86.18,17.95 -85.83,18.7 -85.51,19.45 -85.28,20.2 -85.04,20.98 -84.84,21.77 -84.68,22.56 -84.57,23.39 -84.53,24.17 -84.49,25 -65.51,25
  Keep-Out Layer region: -15.47,24.17 -15.43,23.39 -15.32,22.56 -15.16,21.77 -14.96,20.98 -14.72,20.2 -14.49,19.45 -14.17,18.7 -13.82,17.95 -13.43,17.24 -12.99,16.57 -12.56,15.91 -12.05,15.24 -11.54,14.65 -10.94,14.06 -10.35,13.46 -9.76,12.95 -9.09,12.44 -8.43,12.01 -7.76,11.57 -7.05,11.18 -6.3,10.83 -5.55,10.51 -4.8,10.28 -4.02,10.04 -3.23,9.84 -2.44,9.69 -1.61,9.57 -0.83,9.53 -0.25,9.5 0,9.5 0,9.49 -0.25,9.5 -50,9.49 -49.17,9.53 -48.39,9.57 -47.56,9.69 -46.77,9.84 -45.98,10.04 -45.2,10.28 -44.45,10.51 -43.7,10.83 -42.95,11.18 -42.24,11.57 -41.57,12.01 -40.91,12.44 -40.24,12.95 -39.65,13.46 -39.06,14.06 -38.46,14.65 -37.95,15.24 -37.44,15.91 -37.01,16.57 -36.57,17.24 -36.18,17.95 -35.83,18.7 -35.51,19.45 -35.28,20.2 -35.04,20.98 -34.84,21.77 -34.68,22.56 -34.57,23.39 -34.53,24.17 -34.49,25 -15.51,25
  Keep-Out Layer region: 34.53,24.17 34.57,23.39 34.68,22.56 34.84,21.77 35.04,20.98 35.28,20.2 35.51,19.45 35.83,18.7 36.18,17.95 36.57,17.24 37.01,16.57 37.44,15.91 37.95,15.24 38.46,14.65 39.06,14.06 39.65,13.46 40.24,12.95 40.91,12.44 41.57,12.01 42.24,11.57 42.95,11.18 43.7,10.83 44.45,10.51 45.2,10.28 45.98,10.04 46.77,9.84 47.56,9.69 48.39,9.57 49.17,9.53 49.75,9.5 50,9.5 50,9.49 49.75,9.5 0,9.49 0.83,9.53 1.61,9.57 2.44,9.69 3.23,9.84 4.02,10.04 4.8,10.28 5.55,10.51 6.3,10.83 7.05,11.18 7.76,11.57 8.43,12.01 9.09,12.44 9.76,12.95 10.35,13.46 10.94,14.06 11.54,14.65 12.05,15.24 12.56,15.91 12.99,16.57 13.43,17.24 13.82,17.95 14.17,18.7 14.49,19.45 14.72,20.2 14.96,20.98 15.16,21.77 15.32,22.56 15.43,23.39 15.47,24.17 15.51,25 34.49,25
  Keep-Out Layer region: 84.53,24.17 84.57,23.39 84.68,22.56 84.84,21.77 85.04,20.98 85.28,20.2 85.51,19.45 85.83,18.7 86.18,17.95 86.57,17.24 87.01,16.57 87.44,15.91 87.95,15.24 88.46,14.65 89.06,14.06 89.65,13.46 90.24,12.95 90.91,12.44 91.57,12.01 92.24,11.57 92.95,11.18 93.7,10.83 94.45,10.51 95.2,10.28 95.98,10.04 96.77,9.84 97.56,9.69 98.39,9.57 99.17,9.53 99.75,9.5 100,9.5 100,9.49 99.75,9.5 50,9.49 50.83,9.53 51.61,9.57 52.44,9.69 53.23,9.84 54.02,10.04 54.8,10.28 55.55,10.51 56.3,10.83 57.05,11.18 57.76,11.57 58.43,12.01 59.09,12.44 59.76,12.95 60.35,13.46 60.94,14.06 61.54,14.65 62.05,15.24 62.56,15.91 62.99,16.57 63.43,17.24 63.82,17.95 64.17,18.7 64.49,19.45 64.72,20.2 64.96,20.98 65.16,21.77 65.32,22.56 65.43,23.39 65.47,24.17 65.51,25 84.49,25
  silkscreen extent -243,-177 243,147
WL-TMRC_D5.9H8.7 [mm] "THT Mono-color Round Color LED, 2-leads"
  round 1.5 hole 1: 1(-1.27,0) 2(1.27,0)
  silkscreen extent -3.07,-3.07 2.58,3.08, body extent -2.95,-10.7 2.45,0.25, height 5.94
